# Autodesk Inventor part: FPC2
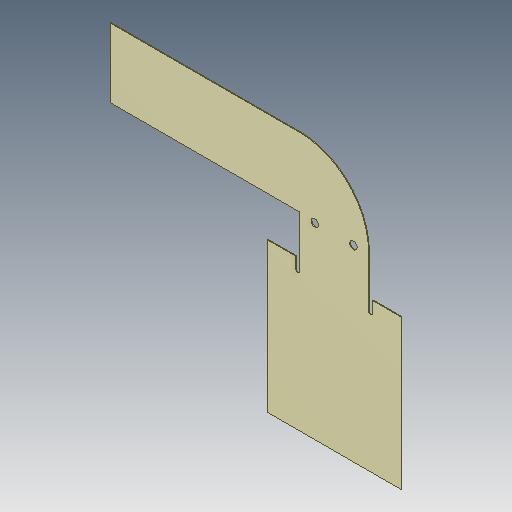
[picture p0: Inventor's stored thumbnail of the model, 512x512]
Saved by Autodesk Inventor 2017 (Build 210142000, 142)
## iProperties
Part Number: FPC2
Material: ポリプロピレン
Document SubType Name: Modeling
Designer: kyushu-hep
Density: 0.899 g/cm^3
Appearance: 滑らか - 灰色
Mass: 0.483015 g
Surface Area: 54.372 cm^2
Volume: 0.53728 cm^3
Author: kyushu-hep
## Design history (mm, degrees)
sketch "スケッチ1"
  geometry: L1 (-4.606, 13.906)-(-4.606, -25.094); L2 (-4.606, -25.094)-(30.394, -25.094); L3 (30.394, -25.094)-(30.394, 13.906); L4 (30.394, 13.906)-(22.894, 13.906); L5 (22.894, 13.906)-(22.894, 10.906); L6 (21.894, 10.906)-(21.894, 24.406); L7 (3.894, 42.406)-(-45.606, 42.406); L8 (-45.606, 42.406)-(-45.606, 24.406); L9 (-45.606, 24.406)-(3.894, 24.406); L10 (3.894, 24.406)-(3.894, 10.906); L11 (2.894, 10.906)-(2.894, 13.906); L12 (2.894, 13.906)-(-4.606, 13.906); A1 r 0.5 centre (22.394, 10.906) between (21.894, 10.906) and (22.894, 10.906); A2 r 18 centre (3.894, 24.406) between (21.894, 24.406) and (3.894, 42.406); A3 r 0.5 centre (3.394, 10.906) between (2.894, 10.906) and (3.894, 10.906); 1 further point
  constraints: 24 end point, 8 perpendicular, 6 point on circle, 6 tangent, 3 centre point, 3 equal length, 2 parallel, 1 horizontal, 1 vertical
  dimensions: "d0" = 39 distance of L1.start L1.end; "d1" = 35 distance of L1.end L2.end; "d2" = 39 distance of L2.end L3.end; "d3" = 13.5 distance of L6.start L6.end; "d4" = 0.5 distance from line of L10 A3.centre; "d5" = 0.5 distance from line of L6 A1.centre; "d6" = 18 distance between parallel lines of L6 L10; "d7" = 3 distance of L4.end L5.end; "d8" = 18 distance from line of L6 A2.centre; "d9" = 76 distance between parallel lines of L3 L8
extrude "押し出し1" new body sketch "スケッチ1" distance "d10" = 0.2; taper "d11" = 0 deg
sketch "スケッチ2"
  geometry: L1 (-4.606, -25.094)-(30.394, -25.094) reference; L2 (3.894, 24.406)-(3.894, 10.906) reference; C1 r 1 at (7.844, 23.906); C2 r 1 at (17.944, 23.906); 1 further point
  constraints: 2 centre point
  dimensions: "d12" = 2 diameter of C1; "d13" = 2 diameter of C2; "d14" = 49 distance from line of C1.centre L1; "d15" = 49 distance from line of C2.centre L1; "d16" = 10.1 distance of C2.centre C1.centre; "d17" = 3.95 distance from line of C1.centre L2
extrude "押し出し2" cut sketch "スケッチ2" distance "d18" = 0.2; taper "d19" = 0 deg
node "ソリッド1"
